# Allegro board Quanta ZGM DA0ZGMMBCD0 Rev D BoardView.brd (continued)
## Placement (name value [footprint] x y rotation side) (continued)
D73  *ESD5311Z-2/TR  [D-0_6X0_3-0_34H]  18.34 16.98 0 bottom
D74  *ESD5311Z-2/TR  [D-0_6X0_3-0_34H]  19.32 16.98 180 bottom
D75  *ESD5311Z-2/TR  [D-0_6X0_3-0_34H]  20.42 16.98 0 bottom
D76  *ESD5311Z-2/TR  [D-0_6X0_3-0_34H]  21.4 16.98 180 bottom
D77  *ESD5311Z-2/TR  [D-0_6X0_3-0_34H]  22.5 16.98 0 bottom
D78  *ESD5311Z-2/TR  [D-0_6X0_3-0_34H]  23.48 16.98 180 bottom
D79  *ESD5311Z-2/TR  [D-0_6X0_3-0_34H]  24.59 16.98 0 bottom
D80  *ESD5311Z-2/TR  [D-0_6X0_3-0_34H]  25.61 16.98 180 bottom
DG1  BAT54AW-L  [SOT23-1_7-65-3P]  245.39 113.12 0 top
DG2  RB500V-40  [D-SOD323-1_85X1_25-0_95H]  262.89 116.55 90 bottom
DG3  RB500V-40  [D-SOD323-1_85X1_25-0_95H]  248.64 116.23 270 bottom
DG4  RB500V-40  [D-SOD323-1_85X1_25-0_95H]  250.52 116.2 90 bottom
DG5  RB500V-40  [D-SOD323-1_85X1_25-0_95H]  252.37 116.2 270 bottom
DG6  RB500V-40  [D-SOD323-1_85X1_25-0_95H]  254.33 116.2 90 bottom
EC1  *10p/25V_2  [C0201]  266.37 191.91 0 bottom
ESD1  *AZ1045-04F.R7G  [ESD10-2_5X1-5-9P-AZ1143]  17.44 9.82 90 top
HOLE1  *H-C94D94N  [H-C94D94N]  155.9 219.35 0 top
HOLE2  *H-C94D94N  [H-C94D94N]  237.9 219.35 0 top
HOLE3  *H-C315D118P2  [H-C315D118P2]  155.9 214.1 0 top
HOLE4  *H-TC315IC158BC236D118P2  [H-TC315IC158BC236D118P2]  197.9 214.1 0 top
HOLE5  *H-TBC315IC158D118P2  [H-TBC315IC158D118P2]  239.9 214.1 0 top
HOLE6  *H-ZGM-3  [H-ZGM-3]  109.9 213.6 0 top
HOLE7  *H-C114D114N  [H-C114D114N]  280.4 213.6 0 top
HOLE8  *H-ZGM-2  [H-ZGM-2]  285.9 213.6 0 top
HOLE9  *H-TC315IC198BC158D158PT  [H-TC315IC198BC158D158PT]  200.54 174.56 0 top
HOLE10  *H-TC315IC198BC158D158PT  [H-TC315IC198BC158D158PT]  273.86 174.56 0 top
HOLE11  *H-TC315IC198BC158D158PT  [H-TC315IC198BC158D158PT]  123.79 167.07 0 top
HOLE12  *H-TC315IC198BC158D158PT  [H-TC315IC198BC158D158PT]  176.59 167.07 0 top
HOLE13  *H-TC315IC158BC236D118P2  [H-TC315IC158BC236D118P2]  286.1 150 0 top
HOLE15  *H-TC315IC198BC158D158PT  [H-TC315IC198BC158D158PT]  200.54 119.58 0 top
HOLE16  *H-TC315IC198BC158D158PT  [H-TC315IC198BC158D158PT]  273.86 119.58 0 top
HOLE17  *H-TC315IC198BC158D158PT  [H-TC315IC198BC158D158PT]  123.79 117.07 0 top
HOLE18  *H-TC315IC198BC158D158PT  [H-TC315IC198BC158D158PT]  176.59 117.07 0 top
HOLE19  *H-C315I158D118P2  [H-C315I158D118P2]  295.72 113.71 0 top
HOLE20  *H-TBC315IC158D118P2  [H-TBC315IC158D118P2]  99.13 109.14 0 top
HOLE21  *H-C315D276P2  [H-C315D276P2]  208.86 90.77 0 top
HOLE22  *H-C315D118P2  [H-C315D118P2]  17.4 87 0 top
HOLE24  *H-TC146IC186BC228D146P2  [H-TC146IC186BC228D146P2]  112.88 71.95 180 bottom
HOLE25  *2d-barcode-8x8-s  [2D-BARCODE-8X8-S]  85.86 69.18 180 top
HOLE26  *H-ZGM-1  [H-ZGM-1]  291.4 63.2 0 top
HOLE27  *H-C315D118P2  [H-C315D118P2]  105.32 42.5 0 top
HOLE28  *H-C315D118P2  [H-C315D118P2]  253.5 42.5 0 top
HOLE29  *H-C315D118P2  [H-C315D118P2]  29 34.5 0 top
HOLE30  *H-C315D118P2  [H-C315D118P2]  10.4 4 0 top
HOLE31  *h-tc228ic174bc134d134pt  [H-TC228IC174BC134D134PT]  25.98 84.43 180 bottom
HOLE32  *H-TC217IC174BC134D134PT  [H-TC217IC174BC134D134PT]  249.41 70.24 180 bottom
HOLE33  *h-tc228ic174bc134d134pt  [H-TC228IC174BC134D134PT]  25.98 59.43 180 bottom
HOLE34  *2d-barcode-8x8-s  [2D-BARCODE-8X8-S]  92.89 45.56 0 bottom
HOLE35  *pad-zgm-1np  [PAD-ZGM-1NP]  280.8 112.87 180 bottom
HOLE36  *pad-zgm-2np  [PAD-ZGM-2NP]  263.02 112.87 180 bottom
HOLE37  *pad-zgm-3np  [PAD-ZGM-3NP]  217.3 112.87 180 bottom
HOLE38  *pad-zgm-4np  [PAD-ZGM-4NP]  181.74 112.87 180 bottom
HOLE39  *pad-zgm-5np  [PAD-ZGM-5NP]  166.5 112.87 180 bottom
HOLE40  *pad-zgm-6np  [PAD-ZGM-6NP]  120.78 112.87 180 bottom
HOLE41  *pad-zgm-7np  [PAD-ZGM-7NP]  118.24 133.19 180 bottom
HOLE42  *pad-zgm-8np  [PAD-ZGM-8NP]  118.24 171.29 180 bottom
HOLE43  *pad-zgm-9np  [PAD-ZGM-9NP]  128.4 171.29 180 bottom
HOLE44  *pad-zgm-10np  [PAD-ZGM-10NP]  161.42 171.29 180 bottom
HOLE45  *pad-zgm-11np  [PAD-ZGM-11NP]  194.44 173.83 180 bottom
HOLE46  *pad-zgm-12np  [PAD-ZGM-12NP]  222.38 189.07 180 bottom
HOLE47  *pad-zgm-13np  [PAD-ZGM-13NP]  247.78 189.07 180 bottom
HOLE48  *pad-zgm-14np  [PAD-ZGM-14NP]  270.64 189.07 180 bottom
HOLE49  *pad-zgm-15np  [PAD-ZGM-15NP]  280.8 171.29 180 bottom
HOLE50  *pad-zgm-16np  [PAD-ZGM-16NP]  280.8 148.43 180 bottom
J1  5G@5-501709002000-6  [SIMCARD-5-501709002000-6-6P]  238.73 68 0 bottom
J2  5G_S@20449-001E-03  [ANTENNA-20449-001E-4P]  270.76 53 90 bottom
J3  5G_S@20449-001E-03  [ANTENNA-20449-001E-4P]  275.76 53 90 bottom
J4  *JUMP  [JOPEN25X30_S]  226.83 51.73 180 bottom
J5  *JUMP  [JOPEN25X30_S]  231.52 47.84 0 bottom
JDIM1  D4AS0-26001-1P80  [DDR4-D4AS0-26001-1P80-STD-260P-SMT]  154.7 100.25 0 bottom
JDIM2  D4AS0-26001-1P40  [DDR4-D4AS0-26001-1P40-STD-260P-SMT]  154.65 85.45 0 bottom
L1  BLM15PD121SN1D_1.3A  [R0402]  55.88 95.72 90 top
L2  0.68uH_2.5x2.0x1.2  [L2_5X2-1_2H]  44.83 94.45 0 top
L3  *NFP0QHB372HS2D  [FILTER-NFG0QHB372HS2D-4P-SMT]  210.52 80.89 270 top
L4  BLM15PD121SN1D_1.3A  [R0402]  48.64 77.81 90 top
L5  PBY160808T-600Y-N_3A  [R0603]  310.56 77.72 90 top
L6  0.68uH_2.5x2.0x1.2  [L2_5X2-1_2H]  40.26 77.18 0 top
L7  BLM15AG121SN1D_0.5A  [R0402]  169.04 75.53 270 top
L8  HCB2012KF-220T60_6A  [R0805]  314.31 74.62 90 top
L9  *SUB@0_5%_6  [R0603]  297.02 72.9 270 top
L10  *SUB@0_5%_6  [R0603]  298.45 74.17 270 top
L11  PBY160808T-600Y-N_3A  [R0603]  305.84 69.52 180 top
L12  HCB1608KF-301T20_2A  [R0603]  14.51 67.98 180 top
L13  BLM15AG121SN1D_0.5A  [R0402]  186.57 64.22 0 top
L14  BLM15AG121SN1D_0.5A  [R0402]  187.96 62.83 90 top
L15  RFL11T2SA0BR  [FILTER-RFL11T2SA0BR-6P]  19.08 56.96 270 top
L16  RFA11T2SA4CR  [FILTER-RFL11T2SA0BR-6P]  18.79 51.82 270 top
L17  *SUB@Short_0603  [S0603]  288.29 74.64 180 bottom
L18  *SUB@Short_0603  [S0603]  288.67 69.94 0 bottom
L19  HCB1608KF-301T20_2A  [R0603]  24.21 66.66 90 bottom
L20  PBY160808T-600Y-N_3A  [R0603]  309.75 61.42 180 bottom
L21  SUB@HCB2012KF-220T60_6A  [R0805]  299.04 60.6 0 bottom
L22  PBY160808T-600Y-N_3A  [R0603]  314.48 60.36 180 bottom
LED1  *B/R/G_LTST-G683GEBW-P2  [LEDLTST-G683GEBW-6P]  197.9 219.15 0 bottom
LED2  *B/R/G_LTST-G683GEBW-P2  [LEDLTST-G683GEBW-6P]  148.9 218.65 0 bottom
LED3  *B/R/G_LTST-G683GEBW-P2  [LEDLTST-G683GEBW-6P]  162 218.65 180 bottom
LED4  *B/R/G_LTST-G683GEBW-P2  [LEDLTST-G683GEBW-6P]  169.9 218.65 0 bottom
LED5  *B/R/G_LTST-G683GEBW-P2  [LEDLTST-G683GEBW-6P]  226.9 218.65 180 bottom
LED6  *B/R/G_LTST-G683GEBW-P2  [LEDLTST-G683GEBW-6P]  233.9 218.65 0 bottom
LED7  *B/R/G_LTST-G683GEBW-P2  [LEDLTST-G683GEBW-6P]  246 218.65 180 bottom
LG1  HCB1005KF-330T30_3A  [R0402]  266.09 136.96 180 top
LG2  HCB1005KF-330T30_3A  [R0402]  225.22 133.59 0 top
LG6  5G@HCB1005KF-330T30_3A  [R0402]  237.32 59.6 180 bottom
LG7  5G@HCB1005KF-330T30_3A  [R0402]  239.47 59.6 0 bottom
LG8  5G@HCB1005KF-330T30_3A  [R0402]  241.61 59.6 0 bottom
NOREF  -  []  115.45 -71.59 0 top
NOREF#2  -  [unnamed#2]  320.17 60.41 0 top
NOREF#3  -  [unnamed#2]  31.24 70.29 0 top
NOREF#4  -  [unnamed#2]  9.66 99.91 0 top
NOREF#5  -  []  88.4 44.31 0 top
NOREF#6  -  [unnamed#2]  285.73 207.73 0 top
NOREF#7  -  [unnamed#2]  41.3 87.34 90 top
NOREF#8  -  []  167.54 -10.4 0 top
NOREF#9  -  []  85.93 55.21 180 bottom
NOREF#10  -  [unnamed#2]  320.32 60.58 180 bottom
NOREF#11  -  [unnamed#2]  283.83 56.35 270 bottom
NOREF#12  -  [unnamed#2]  285.64 207.98 180 bottom
NOREF#13  -  [unnamed#2]  9.67 100.07 180 bottom
PC1  EV@1000p/50V_4  [C0402]  223.86 215.11 0 top
PC2  *EV@0.015u/25V_4  [C0402]  233.9 214.5 0 top
PC3  0.1u/6.3V_2  [C0201]  124.67 213.8 0 top
PC4  EV@1u/6.3V_4  [C0402]  223.05 212.52 90 top
PC5  *0.47u/10V_4  [C0402]  169.89 212.31 0 top
PC6  *EV@0.1u/25V_2  [C0201]  251.34 212.16 0 top
PC7  330p/50V_4  [C0402]  162.97 211.92 90 top
PC8  *0.1u/16V_4  [C0402]  168.06 211.51 270 top
PC9  2.2u/6.3V_4  [C0402]  165.71 210.82 270 top
PC10  330p/25V_4  [C0402]  170.44 210.15 0 top
PC11  G3@0.1u/25V_4  [C0402]  136.24 209.84 180 top
PC12  330p/25V_4  [C0402]  169.42 209.18 180 top
PC13  33p/50V_4  [C0402]  168.02 209 270 top
PC14  6800p/50V_4  [C0402]  161.53 208.09 180 top
PC15  EV@0.1u/50V_4  [C0402]  228.94 208.07 0 top
PC16  EV@680p/50V_4  [C0402]  226.57 207.71 270 top
PC17  EV@0.1u/50V_4  [C0402]  256.72 206.23 90 top
PC18  EV@2200p/50V_4  [C0402]  255.63 206.23 90 top
PC19  EV@0.1u/50V_4  [C0402]  254.53 206.23 90 top
PC20  0.1u/25V_4  [C0402]  167.95 206.13 270 top
PC21  EV@2200p/50V_4  [C0402]  238.98 206.09 90 top
PC22  EV@0.1u/50V_4  [C0402]  241 206.07 90 top
PC23  EV@0.1u/50V_4  [C0402]  239.98 206.07 90 top
PC24  *EV@0.015u/25V_4  [C0402]  225.89 205.98 270 top
PC25  0.1u/50V_4  [C0402]  172.42 205.09 180 top
PC26  2.2u/6.3V_4  [C0402]  162.31 204.69 0 top
PC27  EV@10u/25V_8  [C0805]  248.29 204.64 90 top
PC28  EV@10u/25V_8  [C0805]  252.62 204.64 90 top
PC29  0.22u/25V_4  [C0402]  163.83 203.32 90 top
PC30  *EV@2200p/50V_4  [C0402]  233.43 200.43 0 top
PC31  *EV@47u/6.3V_6  [C0603]  243.63 196.57 270 top
PC32  10u/25V_8  [C0805]  173.99 196.57 90 top
PC33  *EV@47u/6.3V_6  [C0603]  242.17 196.56 270 top
PC34  EV@47u/6.3V_6  [C0603]  245.08 196.55 270 top
PC35  2200p/50V_4  [C0402]  175.52 196.3 90 top
PC36  EV@330u/2V_7343H1.9  [CC7343]  253.02 195.17 90 top
PC37  EV@330u/2V_7343H1.9  [CC7343]  248.24 195.17 90 top
PC38  EV@330u/2V_7343H1.9  [CC7343]  234.17 195.14 90 top
PC39  EV@330u/2V_7343H1.9  [CC7343]  238.92 195.14 90 top
PC40  10u/25V_8  [C0805]  118.11 194.65 90 top
PC41  10u/25V_8  [C0805]  127.77 194.65 90 top
PC42  10u/25V_8  [C0805]  137.42 194.65 90 top
PC43  10u/25V_8  [C0805]  147.07 194.65 90 top
PC44  10u/25V_8  [C0805]  156.72 194.65 90 top
PC45  10u/25V_8  [C0805]  166.37 194.65 90 top
PC46  *2200p/50V_4  [C0402]  175.36 193.03 270 top
PC47  G3@0.1u/25V_2  [C0201]  227.72 191.71 90 top
PC48  G3@0.1u/25V_2  [C0201]  229.01 191.03 90 top
PC49  G3@0.1u/25V_2  [C0201]  227.72 190.71 90 top
PC50  *EV@47u/6.3V_6  [C0603]  243.69 190.67 90 top
PC51  *EV@47u/6.3V_6  [C0603]  242.24 190.67 90 top
PC52  EV@47u/6.3V_6  [C0603]  245.13 190.67 90 top
PC53  G3@0.1u/25V_4  [C0402]  223.19 189.07 270 top
PC54  G3@0.1u/25V_4  [C0402]  227.65 188.44 270 top
PC55  1000p/50V_4  [C0402]  116.97 188.3 0 top
PC56  1000p/50V_4  [C0402]  126.62 188.3 0 top
PC57  1000p/50V_4  [C0402]  136.4 188.3 0 top
PC58  1000p/50V_4  [C0402]  155.71 188.3 0 top
PC59  1000p/50V_4  [C0402]  165.23 188.3 0 top
PC60  1000p/50V_4  [C0402]  145.93 188.18 0 top
PC61  330u/2.5V_7343H1.9  [CC7343]  168.94 185.85 90 top
PC62  *330u/2.5V_7343H1.9  [CC7343]  173.88 185.75 90 top
PC63  330u/2V_7343H1.9  [CC7343]  123.7 182.84 90 top
PC64  *330u/2V_7343H1.9  [CC7343]  133.35 182.84 90 top
PC65  330u/2V_7343H1.9  [CC7343]  143.01 182.84 90 top
PC66  330u/2V_7343H1.9  [CC7343]  152.66 182.84 90 top
PC67  220u/2V_7343H1.0  [CC7343]  143.07 140.99 0 top
PC68  220u/2V_7343H1.0  [CC7343]  143.07 145.75 0 top
PC69  22u/6.3V_6  [C0603]  174.7 179.76 180 top
PC70  22u/6.3V_6  [C0603]  168.97 179.72 0 top
PC71  22u/6.3V_8  [C0805]  111.67 179.04 270 top
PC72  22u/6.3V_8  [C0805]  165.8 179.03 270 top
PC73  22u/6.3V_8  [C0805]  118.38 178.92 270 top
PC74  22u/6.3V_8  [C0805]  120.36 178.92 270 top
PC75  22u/6.3V_8  [C0805]  146.82 178.91 270 top
PC76  22u/6.3V_8  [C0805]  149.23 178.91 270 top
PC77  22u/6.3V_8  [C0805]  156.47 178.91 270 top
PC78  22u/6.3V_8  [C0805]  158.88 178.91 270 top
PC79  22u/6.3V_8  [C0805]  127.38 178.78 270 top
PC80  22u/6.3V_8  [C0805]  129.8 178.78 270 top
PC81  22u/6.3V_8  [C0805]  137.16 178.78 270 top
PC82  22u/6.3V_8  [C0805]  139.58 178.78 270 top
PC83  22u/6.3V_6  [C0603]  168.92 177.89 0 top
PC84  22u/6.3V_6  [C0603]  174.82 177.81 180 top
PC85  22u/6.3V_6  [C0603]  168.89 176.08 0 top
PC86  0.1u/50V_4  [C0402]  158.32 175.21 90 top
PC87  0.1u/50V_4  [C0402]  111.33 175.2 90 top
PC88  0.1u/50V_4  [C0402]  130.17 175.2 90 top
PC89  0.1u/50V_4  [C0402]  139.31 175.2 90 top
PC90  0.1u/50V_4  [C0402]  120.25 175.2 90 top
PC91  0.1u/50V_4  [C0402]  149.21 175.2 90 top
PC92  EV@0.1u/16V_4  [C0402]  283.34 130.21 90 top
PC93  *EV@22u/6.3V_6  [C0603]  286.13 130.13 90 top
PC94  EV@22u/6.3V_6  [C0603]  284.67 130.13 90 top
PC95  EV@22u/6.3V_6  [C0603]  287.59 130.12 90 top
PC96  EV@2.2u/10V_4  [C0402]  290.38 124.97 180 top
PC97  EV@0.1u/25V_4  [C0402]  286.04 123.9 180 top
PC98  EV@1u/6.3V_4  [C0402]  291.92 122.78 180 top
PC99  EV@330p/25V_2  [C0201]  291.61 121.85 180 top
PC100  EV@22u/6.3V_6  [C0603]  284.12 121.15 0 top
PC101  EV@0.1u/16V_4  [C0402]  290.43 119.26 270 top
PC102  *EV@2200p/50V_4  [C0402]  289.96 116.93 90 top
PC103  EV@330u/2V_7343H1.9  [CC7343]  232.29 103.98 270 top
PC104  EV@330u/2V_7343H1.9  [CC7343]  238 103.98 270 top
PC105  EV@330u/2V_7343H1.9  [CC7343]  242.83 103.98 270 top
PC106  EV@330u/2V_7343H1.9  [CC7343]  247.78 103.98 270 top
PC107  EV@330u/2V_7343H1.9  [CC7343]  252.61 103.98 270 top
PC108  EV@330u/2V_7343H1.9  [CC7343]  257.56 103.98 270 top
PC109  EV@330u/2V_7343H1.9  [CC7343]  262.39 103.98 270 top
PC110  EV@330u/2V_7343H1.9  [CC7343]  267.34 103.98 270 top
PC111  EV@330u/2V_7343H1.9  [CC7343]  272.16 103.98 270 top
PC112  EV@330u/2V_7343H1.9  [CC7343]  276.99 103.98 270 top
PC113  EV@330u/2V_7343H1.9  [CC7343]  281.82 103.98 270 top
PC114  G3@330u/2V_7343H1.9  [CC7343]  286.9 103.98 270 top
PC115  G3@330u/2V_7343H1.9  [CC7343]  291.72 103.98 270 top
PC116  5G@0.1u/16V_4  [C0402]  301.26 103.97 180 top
PC117  EV@330u/2V_7343H1.9  [CC7343]  227.41 103.93 270 top
PC118  EV@330u/2V_7343H1.9  [CC7343]  215.12 103.9 270 top
PC119  EV@330u/2V_7343H1.9  [CC7343]  219.99 103.87 270 top
PC120  EV@0.1u/50V_4  [C0402]  198.36 103.37 270 top
PC121  5G@330p/25V_2  [C0201]  295.81 102.1 0 top
PC122  5G@22u/6.3V_6  [C0603]  301.72 102.7 180 top
PC123  10u/25V_6  [C0603]  97.48 94.99 180 top
PC124  10u/25V_6  [C0603]  85.98 93.31 270 top
PC125  10u/25V_6  [C0603]  87.51 93.31 270 top
PC126  EV@10u/25V_8  [C0805]  224.79 93.31 270 top
PC127  EV@10u/25V_8  [C0805]  234.57 93.31 270 top
PC128  EV@10u/25V_8  [C0805]  244.35 93.31 270 top
PC129  EV@10u/25V_8  [C0805]  254.13 93.31 270 top
PC130  EV@10u/25V_8  [C0805]  263.91 93.31 270 top
PC131  EV@10u/25V_8  [C0805]  273.69 93.31 270 top
PC132  G3@10u/25V_8  [C0805]  292.75 93.29 270 top
PC133  EV@10u/25V_8  [C0805]  283.72 93.18 270 top
PC134  10u/25V_6  [C0603]  97.48 93.56 180 top
PC135  0.1u/25V_4  [C0402]  89.49 93.05 270 top
PC136  10u/25V_6  [C0603]  96.67 90.96 180 top
PC137  G3@10u/25V_8  [C0805]  292.74 90.03 90 top
PC138  EV@10u/25V_8  [C0805]  224.79 90.01 90 top
PC139  EV@10u/25V_8  [C0805]  234.57 90.01 90 top
PC140  EV@10u/25V_8  [C0805]  244.35 90.01 90 top
PC141  EV@10u/25V_8  [C0805]  254.13 90.01 90 top
PC142  EV@10u/25V_8  [C0805]  263.91 90.01 90 top
PC143  EV@10u/25V_8  [C0805]  273.69 90.01 90 top
PC144  EV@10u/25V_8  [C0805]  283.72 89.88 90 top
PC145  10u/25V_6  [C0603]  96.67 89.53 180 top
PC146  0.1u/25V_4  [C0402]  88.56 89.26 180 top
PC147  G3@0.1u/50V_4  [C0402]  291.24 88.91 90 top
PC148  EV@0.1u/50V_4  [C0402]  282.07 89.12 90 top
PC149  0.1u/25V_4  [C0402]  97.14 86.96 270 top
PC150  4.7u/6.3V_4  [C0402_2]  89.39 85.19 90 top
PC151  10p/50V_4  [C0402]  92.08 85.18 90 top
PC152  2200p/25V_2  [C0201]  93.48 84.14 270 top
PC153  EV@1u/10V_2  [C0201]  262.51 83.91 270 top
PC154  *EV@1500p/50V_4  [C0402]  264.67 83.53 90 top
PC155  *EV@0.047u/25V_4  [C0402]  277.7 83.4 90 top
PC156  EV@33u/25V_7343H1.9  [CC7343]  241.47 83.02 180 top
PC157  EV@4700p/50V_4  [C0402]  267.97 81.88 0 top
PC158  EV@4.7u/6.3V_2  [C0201]  256.59 80.51 90 top
PC159  EV_SP@220p/50V_2  [C0201]  251.72 79.85 0 top
PC160  EV@220p/50V_2  [C0201]  251.73 79.04 0 top
PC161  EV@220p/50V_2  [C0201]  251.74 77.95 0 top
PC162  EV@220p/50V_2  [C0201]  251.72 77.19 180 top
PC163  EV@0.1u/25V_4  [C0402]  266.07 76.29 180 top
PC164  EV@220p/50V_2  [C0201]  251.73 76.1 0 top
PC165  *EV@0.015u/25V_4  [C0402]  267.47 75.65 270 top
PC166  1000p/50V_2  [C0201]  130.43 75.48 90 top
PC167  1000p/50V_2  [C0201]  131.19 75.48 90 top
PC168  EV@220p/50V_2  [C0201]  251.72 75.34 180 top
PC169  *EV@0.015u/25V_4  [C0402]  266.07 75.32 0 top
PC170  1000p/50V_2  [C0201]  144.15 74.61 90 top
PC171  1000p/50V_2  [C0201]  144.91 74.61 90 top
PC172  1000p/50V_2  [C0201]  55.63 74.26 90 top
PC173  1000p/50V_2  [C0201]  56.39 74.26 90 top
PC174  EV@220p/50V_2  [C0201]  251.72 74.26 0 top
PC175  10u/6.3V_4  [C0402_2]  127.64 74.13 90 top
PC176  0.1u/50V_4  [C0402]  128.78 74.13 90 top
PC177  10u/6.3V_4  [C0402_2]  133.53 74.13 90 top
PC178  0.1u/50V_4  [C0402]  134.62 74.13 90 top
PC179  *EV@0.1u/25V_2  [C0201]  265.81 74.05 0 top
PC180  *EV@0.1u/25V_2  [C0201]  266.96 74.03 180 top
PC181  EV@220p/50V_2  [C0201]  251.72 73.44 180 top
PC182  10u/6.3V_4  [C0402_2]  141.35 73.24 90 top
PC183  0.1u/50V_4  [C0402]  142.5 73.24 90 top
PC184  10u/6.3V_4  [C0402_2]  147.25 73.24 90 top
PC185  0.1u/50V_4  [C0402]  148.34 73.24 90 top
PC186  10u/6.3V_4  [C0402_2]  52.33 72.66 90 top
PC187  0.1u/50V_4  [C0402]  53.47 72.66 90 top
PC188  *EV@1000p/50V_2  [C0201]  263.91 72.48 270 top
PC189  1u/25V_4  [C0402]  128.53 72.38 270 top
PC190  1u/25V_4  [C0402]  133.61 72.35 270 top
PC191  EV@1u/6.3V_2  [C0201]  257.18 72.35 270 top
PC192  EV@0.015u/25V_4  [C0402]  264.8 72.1 270 top
PC193  *EV@1000p/50V_2  [C0201]  259.72 71.97 270 top
PC194  *EV@1000p/50V_2  [C0201]  265.69 71.97 90 top
PC195  EV@0.1u/50V_4  [C0402]  262.39 71.59 180 top
PC196  1u/25V_4  [C0402]  142.5 71.46 270 top
PC197  1u/25V_4  [C0402]  147.25 71.39 270 top
PC198  1u/25V_4  [C0402]  58.17 71.06 270 top
PC199  1u/25V_4  [C0402]  53.47 70.93 270 top
PC200  *0.1u/50V_4  [C0402]  129.82 70.6 90 top
PC201  0.1u/50V_4  [C0402]  130.8 70.59 90 top
PC202  *0.1u/50V_4  [C0402]  132.6 70.52 90 top
PC203  0.1u/50V_4  [C0402]  144.58 69.59 90 top
PC204  *0.1u/50V_4  [C0402]  143.61 69.58 90 top
PC205  *0.1u/50V_4  [C0402]  147.05 69.57 90 top
PC206  *0.1u/50V_4  [C0402]  54.54 68.89 90 top
PC207  *2200p/50V_4  [C0402]  263.44 67.49 90 top
PC208  10u/6.3V_4  [C0402_2]  267.22 64.99 180 top
PC209  0.01u/50V_4  [C0402]  267.22 63.83 180 top
PC210  4.7u/6.3V_2  [C0201]  154.05 61.99 90 top
PC211  *22p/50V_4  [C0402]  265.05 61.31 270 top
PC212  0.1u/50V_4  [C0402]  157.18 59.53 180 top
PC213  0.1u/50V_4  [C0402]  149.99 59.4 0 top
PC214  2200p/50V_4  [C0402]  250.96 58.66 0 top
PC215  10u/6.3V_6  [C0603]  66.27 56.85 270 top
PC216  0.1u/50V_4  [C0402]  67.47 56.46 270 top
PC217  1000p/50V_4  [C0402]  68.49 56.46 270 top
PC218  1000p/50V_4  [C0402]  69.51 56.46 270 top
PC219  0.1u/50V_4  [C0402]  152.76 55.18 180 top
PC220  10u/6.3V_4  [C0402_2]  155.12 55.03 180 top
PC221  *2200p/50V_4  [C0402]  53.63 54.67 270 top
PC222  *680p/50V_6  [C0603]  152.58 51.73 180 top
PC223  0.1u/50V_4  [C0402]  172.01 51.69 180 top
PC224  *680p/50V_6  [C0603]  160.89 51.63 0 top
PC225  0.1u/50V_4  [C0402]  69.65 51.19 270 top
PC226  0.1u/50V_4  [C0402]  71.68 51.19 90 top
PC227  0.1u/50V_4  [C0402]  67.9 50.89 90 top
PC228  1u/25V_4  [C0402]  66.61 50.68 90 top
PC229  0.1u/50V_4  [C0402]  48.28 50.5 270 top
PC230  2200p/50V_4  [C0402]  49.25 50.5 270 top
PC231  680p/50V_4  [C0402]  50.22 50.5 90 top
PC232  1000p/50V_4  [C0402]  51.2 50.5 270 top
PC233  22u/6.3V_8  [C0805]  127.1 48.5 90 top
PC234  22u/6.3V_8  [C0805]  129.11 48.5 90 top
PC235  0.1u/50V_4  [C0402]  39.5 47.46 90 top
PC236  0.1u/50V_4  [C0402]  40.9 47.46 270 top
PC237  0.1u/50V_4  [C0402]  57.78 47.36 270 top
PC238  0.01u/50V_4  [C0402]  36.5 46.45 270 top
PC239  0.1u/50V_4  [C0402]  39.88 46.06 180 top
PC240  330u/2V_7343H1.9  [CC7343]  132.49 45.38 270 top
PC241  *0.01u/50V_4  [C0402]  59.21 45.32 90 top
PC242  100p/50V_2  [C0201]  33.91 45.17 0 top
PC243  0.47u/25V_4  [C0402]  42.55 44.81 180 top
PC244  100p/50V_2  [C0201]  33.79 44.03 0 top
PC245  0.1u/25V_4  [C0402]  238.38 43.52 180 top
PC246  10u/25V_6  [C0603]  245.41 42.96 270 top
PC247  22u/25V_8  [C0805]  62.23 42.63 90 top
PC248  22u/25V_8  [C0805]  64.27 42.63 90 top
PC249  *22u/25V_8  [C0805]  66.3 42.63 90 top
PC250  *22u/25V_8  [C0805]  68.33 42.63 90 top
PC251  0.1u/50V_6  [C0603]  70.06 42.63 90 top
PC252  *100p/50V_4  [C0402]  59.67 42.51 90 top
PC253  2200p/50V_4  [C0402]  60.71 42.51 90 top
PC254  2200p/25V_2  [C0201]  246.59 42.33 90 top
PC255  220u/2.5V_7343H1.0  [CC7343]  232.46 42.3 0 top
PC256  *47p/50V_4  [C0402]  73.66 42 90 top
PC257  *47p/50V_4  [C0402]  76.97 42 90 top
PC258  0.1u/50V_4  [C0402]  125.94 41.6 180 top
PC259  0.047u/50V_4  [C0402]  42.85 41.19 0 top
PC260  *100p/50V_2  [C0201]  33.23 41.03 90 top
PC261  10u/25V_6  [C0603]  245.51 40.28 90 top
PC262  10u/25V_8  [C0805]  126.68 40.1 180 top
PC263  0.01u/50V_4  [C0402]  41.14 39.84 270 top
PC264  2.2u/10V_4  [C0402]  42.16 39.84 90 top
PC265  0.1u/25V_4  [C0402]  246.7 39.38 90 top
PC266  0.1u/25V_2  [C0201]  39.43 39.37 180 top
PC267  0.1u/25V_2  [C0201]  38.45 39.37 0 top
PC268  *680p/50V_6  [C0603]  132.93 39.25 180 top
PC269  *22u/6.3V_6  [C0603]  233.94 39.21 180 top
PC270  *680p/50V_6  [C0603]  53.22 38.82 180 top
PC271  0.1u/25V_4  [C0402]  238.13 38.7 0 top
PC272  0.1u/25V_2  [C0201]  38.97 38.66 180 top
PC273  *22u/6.3V_6  [C0603]  226.75 38.19 90 top
PC274  *22u/6.3V_6  [C0603]  228.22 38.19 90 top
PC275  *22u/6.3V_6  [C0603]  229.67 38.19 90 top
PC276  22u/6.3V_6  [C0603]  233.94 37.78 180 top
PC277  *2200p/25V_2  [C0201]  234.95 36.64 0 top
PC278  0.1u/16V_4  [C0402]  117.22 216.75 180 bottom
PC279  EV@1u/25V_4  [C0402]  252.62 216.35 90 bottom
PC280  *100p/50V_4  [C0402]  124.47 215.94 270 bottom
PC281  *EV@0.1u/25V_2  [C0201]  251.62 215.39 0 bottom
PC282  EV@0.1u/25V_4  [C0402]  250.65 215.26 270 bottom
PC283  EV@1000p/50V_4  [C0402]  223.18 215.02 0 bottom
PC284  2.2u/10V_4  [C0402]  116.93 214.78 270 bottom
PC285  *EV@56p/25V_2  [C0201]  253.72 214.68 90 bottom
PC286  EV@1000p/50V_4  [C0402]  246.78 214.63 0 bottom
PC287  1000p/50V_4  [C0402]  124.84 214.59 180 bottom
PC288  *100p/50V_4  [C0402]  126.62 214.59 180 bottom
PC289  *EV@56p/25V_2  [C0201]  252.22 214.53 90 bottom
PC290  *0.1u/6.3V_2  [C0201]  122.38 214.39 270 bottom
PC291  *0.1u/6.3V_2  [C0201]  123.1 214.39 270 bottom
PC292  *EV@1000p/50V_4  [C0402]  228.04 214.07 90 bottom
PC293  G3@680p/50V_4  [C0402]  223.18 214.05 0 bottom
PC294  *EV@56p/25V_2  [C0201]  252.12 213.67 180 bottom
PC295  2200p/50V_4  [C0402]  124.84 213.58 0 bottom
PC296  G3@1000p/50V_4  [C0402]  223.18 213.08 180 bottom
PC297  0.01u/50V_4  [C0402]  115.31 212.99 180 bottom
PC298  *EV@1000p/16V_2  [C0201]  252.74 212.92 0 bottom
PC299  470p/25V_2  [C0201]  124.46 212.69 180 bottom
PC300  G3@0.1u/50V_4  [C0402]  223.18 212.12 180 bottom
PC301  470p/50V_4  [C0402]  124.83 211.65 180 bottom
PC302  *EV@820p/50V_4  [C0402]  245.89 211.49 0 bottom
PC303  *EV@0.015u/25V_4  [C0402]  231.42 211.37 180 bottom
PC304  G3@2200p/50V_4  [C0402]  223.18 211.15 180 bottom
PC305  *1000p/25V_2  [C0201]  115.58 210.19 0 bottom
PC306  G3@0.1u/50V_4  [C0402]  223.18 210.19 180 bottom
PC307  *EV@1000p/50V_4  [C0402]  229.58 210 270 bottom
PC308  *EV@1000p/50V_4  [C0402]  228.35 209.98 270 bottom
PC309  *EV@0.015u/25V_4  [C0402]  230.57 210.02 90 bottom
PC310  EV@0.22u/25V_4  [C0402]  252.72 209.79 180 bottom
PC311  2200p/50V_4  [C0402]  126.88 209.77 0 bottom
PC312  0.1u/50V_4  [C0402]  172.85 209.69 180 bottom
PC313  47p/50V_4  [C0402]  124.83 209.62 0 bottom
PC314  EV@0.22u/25V_4  [C0402]  247.14 209.46 0 bottom
PC315  1000p/50V_4  [C0402]  172.84 208.71 180 bottom
PC316  220p/50V_4  [C0402]  125.18 208.25 90 bottom
PC317  2200p/50V_4  [C0402]  126.14 208.25 90 bottom
PC318  0.1u/50V_4  [C0402]  172.83 207.74 180 bottom
PC319  33u/25V_7343H1.9  [CC7343]  132.08 207.73 90 bottom
PC320  0.1u/25V_4  [C0402]  115.21 207.43 180 bottom
PC321  EV@2.2u/10V_4  [C0402]  249.95 207.35 180 bottom
PC322  2200p/50V_4  [C0402]  172.82 206.77 180 bottom
PC323  0.1u/25V_4  [C0402]  121.24 205.96 90 bottom
PC324  0.01u/50V_4  [C0402]  122.22 205.96 90 bottom
PC325  0.1u/25V_4  [C0402]  120.04 205.95 90 bottom
PC326  0.1u/25V_4  [C0402]  117.65 205.94 90 bottom
PC327  0.1u/25V_4  [C0402]  118.81 205.94 90 bottom
PC328  0.1u/25V_4  [C0402]  116.44 205.93 90 bottom
PC329  0.1u/25V_4  [C0402]  115.29 205.92 90 bottom
PC330  680p/50V_4  [C0402]  172.84 205.8 0 bottom
PC331  *EV@2200p/50V_4  [C0402]  266.18 204.64 0 bottom
PC332  EV@10u/25V_6  [C0603]  248.3 204.59 90 bottom
PC333  EV@10u/25V_6  [C0603]  252.68 204.59 90 bottom
PC334  G3@1u/25V_4  [C0402]  225.68 203.72 270 bottom
PC335  0.22u/25V_6  [C0603]  116.18 199.56 90 bottom
PC336  0.22u/25V_6  [C0603]  125.71 199.84 90 bottom
PC337  0.22u/25V_6  [C0603]  164.32 199.58 90 bottom
PC338  0.22u/25V_6  [C0603]  135.33 199.66 90 bottom
PC339  0.22u/25V_6  [C0603]  145.21 199.66 90 bottom
PC340  0.22u/25V_6  [C0603]  154.66 199.48 90 bottom
PC341  2.2u/10V_4  [C0402]  113.29 198.97 270 bottom
PC342  2.2u/10V_4  [C0402]  122.94 198.97 90 bottom
PC343  2.2u/10V_4  [C0402]  132.59 198.97 90 bottom
PC344  2.2u/10V_4  [C0402]  142.24 198.97 90 bottom
PC345  2.2u/10V_4  [C0402]  151.9 198.97 90 bottom
PC346  2.2u/10V_4  [C0402]  161.55 198.97 90 bottom
PC347  0.1u/50V_4  [C0402]  118.11 198.34 180 bottom
PC348  0.1u/50V_4  [C0402]  127.77 198.34 180 bottom
PC349  0.1u/50V_4  [C0402]  137.42 198.34 180 bottom
PC350  0.1u/50V_4  [C0402]  147.07 198.34 180 bottom
PC351  0.1u/50V_4  [C0402]  156.72 198.34 180 bottom
PC352  0.1u/50V_4  [C0402]  166.37 198.34 180 bottom
PC353  *G3@0.1u/50V_6  [C0603]  218.04 198.02 90 bottom
PC354  2200p/50V_4  [C0402]  118.11 197.19 180 bottom
PC355  2200p/50V_4  [C0402]  127.77 197.19 180 bottom
PC356  2200p/50V_4  [C0402]  137.42 197.19 180 bottom
PC357  2200p/50V_4  [C0402]  147.07 197.19 180 bottom
PC358  2200p/50V_4  [C0402]  156.72 197.19 180 bottom
PC359  2200p/50V_4  [C0402]  166.37 197.19 180 bottom
PC360  *G3@0.1u/50V_6  [C0603]  201.73 197 90 bottom
PC361  10u/25V_8  [C0805]  174.03 196.58 90 bottom
PC362  0.1u/50V_4  [C0402]  175.52 196.3 90 bottom
PC363  *0.1u/25V_4  [C0402]  176.96 195.67 90 bottom
PC364  *0.1u/50V_6  [C0603]  187.01 195.62 0 bottom
PC365  2.2u/10V_4  [C0402]  110.11 195.42 90 bottom
PC366  2.2u/10V_4  [C0402]  119.76 195.42 90 bottom
PC367  2.2u/10V_4  [C0402]  129.42 195.42 90 bottom
PC368  2.2u/10V_4  [C0402]  139.07 195.42 90 bottom
PC369  2.2u/10V_4  [C0402]  148.72 195.42 90 bottom
PC370  2.2u/10V_4  [C0402]  158.37 195.42 90 bottom
PC371  10u/25V_6  [C0603]  118.11 194.65 90 bottom
PC372  10u/25V_6  [C0603]  127.77 194.65 90 bottom
PC373  10u/25V_6  [C0603]  137.42 194.65 90 bottom
PC374  10u/25V_6  [C0603]  147.07 194.65 90 bottom
PC375  10u/25V_6  [C0603]  156.72 194.65 90 bottom
PC376  10u/25V_6  [C0603]  166.37 194.65 90 bottom
PC377  0.047u/50V_6  [C0603]  184.15 194.61 180 bottom
PC378  *G3@0.1u/25V_4  [C0402]  219.65 193.43 270 bottom
PC379  *G3@0.1u/25V_4  [C0402]  200.65 192.96 90 bottom
PC380  *G3@0.1u/25V_4  [C0402]  214.99 192.94 270 bottom
PC381  *G3@0.1u/25V_4  [C0402]  198.64 192.47 180 bottom
PC382  G3@1u/25V_4  [C0402]  192.91 191.59 180 bottom
PC383  1000p/50V_4  [C0402]  186.29 187.82 0 bottom
PC384  1u/25V_4  [C0402]  188.17 187.82 180 bottom
PC385  22u/6.3V_6  [C0603]  174.73 179.75 180 bottom
PC386  22u/6.3V_6  [C0603]  168.95 179.73 0 bottom
PC387  *G3@0.1u/25V_4  [C0402]  178.67 179.41 0 bottom
PC388  *G3@0.1u/25V_4  [C0402]  177.11 177.95 270 bottom
PC389  22u/6.3V_6  [C0603]  168.95 177.89 0 bottom
PC390  22u/6.3V_6  [C0603]  174.77 177.81 180 bottom
PC391  22u/6.3V_6  [C0603]  168.89 176.09 0 bottom
PC392  *G3@0.1u/50V_4  [C0402]  184.25 175.38 90 bottom
PC393  0.1u/50V_4  [C0402]  108.59 129.63 180 bottom
PC394  EV@22u/6.3V_6  [C0603]  284 121.3 0 bottom
PC395  EV@0.1u/16V_4  [C0402]  284.58 119.45 0 bottom
PC396  *5G@2200p/50V_4  [C0402]  298.05 104.56 90 bottom
PC397  5G@0.1u/16V_4  [C0402]  297.09 104.42 270 bottom
PC398  EV@0.01u/50V_4  [C0402]  198.94 105.71 0 bottom
PC399  5G@1u/6.3V_4  [C0402]  295.25 103.75 0 bottom
PC400  EV@0.1u/50V_4  [C0402]  203.66 103.67 90 bottom
PC401  5G@22u/6.3V_6  [C0603]  301.73 102.71 180 bottom
PC402  5G@2.2u/10V_4  [C0402]  297.68 102.66 270 bottom
PC403  EV@0.1u/50V_4  [C0402]  207.91 101.78 90 bottom
PC404  EV@10u/6.3V_4  [C0402_2]  206.82 101.78 90 bottom
PC405  EV@10u/6.3V_4  [C0402_2]  205.61 101.77 90 bottom
PC406  5G@0.1u/16V_4  [C0402]  295.19 102.41 270 bottom
PC407  5G@22u/6.3V_6  [C0603]  296.66 100.79 180 bottom
PC408  EV@10u/6.3V_4  [C0402_2]  202.02 100.39 180 bottom
PC409  5G@0.1u/25V_4  [C0402]  299.08 100.17 270 bottom
PC410  EV@0.1u/50V_4  [C0402]  202.02 99.3 180 bottom
PC411  5G@22u/6.3V_6  [C0603]  296.63 99.36 180 bottom
PC412  *5G@22u/6.3V_6  [C0603]  296.61 97.93 180 bottom
PC413  EV@2200p/50V_4  [C0402]  282.55 97.63 90 bottom
PC414  G3@2200p/50V_4  [C0402]  294.14 97.63 90 bottom
PC415  EV@2200p/50V_4  [C0402]  234.93 97.5 90 bottom
PC416  EV@2200p/50V_4  [C0402]  244.45 97.5 90 bottom
PC417  EV@2200p/50V_4  [C0402]  253.98 97.5 90 bottom
PC418  EV@2200p/50V_4  [C0402]  263.5 97.5 90 bottom
PC419  EV@2200p/50V_4  [C0402]  273.03 97.5 90 bottom
PC420  EV@2200p/50V_4  [C0402]  225.34 97.4 90 bottom
PC421  0.1u/50V_4  [C0402]  199.72 96.43 0 bottom
PC422  *10u/6.3V_6  [C0603]  199.74 95.24 0 bottom
PC423  10u/6.3V_6  [C0603]  199.74 93.79 0 bottom
PC424  *0.47u/6.3V_4  [C0402]  197.41 93.69 0 bottom
PC425  G3@10u/25V_6  [C0603]  293.41 93.61 270 bottom
PC426  EV@10u/25V_6  [C0603]  224.46 93.43 270 bottom
PC427  EV@10u/25V_6  [C0603]  244.02 93.43 270 bottom
PC428  EV@2200p/50V_4  [C0402]  264.85 93.43 90 bottom
PC429  EV@2.2u/10V_4  [C0402]  275.73 93.42 270 bottom
PC430  G3@2.2u/10V_4  [C0402]  285.64 93.4 270 bottom
PC431  EV@2200p/50V_4  [C0402]  245.29 93.31 90 bottom
PC432  EV@10u/25V_6  [C0603]  263.58 93.31 270 bottom
PC433  EV@2200p/50V_4  [C0402]  225.73 93.18 90 bottom
PC434  EV@10u/25V_6  [C0603]  234.24 93.18 270 bottom
PC435  EV@2200p/50V_4  [C0402]  235.51 93.18 90 bottom
PC436  EV@10u/25V_6  [C0603]  253.8 93.18 270 bottom
PC437  EV@2200p/50V_4  [C0402]  255.07 93.18 90 bottom
PC438  EV@10u/25V_6  [C0603]  273.36 93.18 270 bottom
PC439  EV@2200p/50V_4  [C0402]  274.63 93.05 90 bottom
PC440  EV@10u/25V_6  [C0603]  283.39 93.05 270 bottom
PC441  EV@0.1u/50V_4  [C0402]  284.66 93.05 270 bottom
PC442  G3@0.1u/50V_4  [C0402]  294.64 93.05 270 bottom
PC443  EV@2.2u/10V_4  [C0402]  216.92 92.42 270 bottom
PC444  EV@2.2u/10V_4  [C0402]  246.26 92.37 270 bottom
PC445  EV@2.2u/10V_4  [C0402]  256.04 92.37 270 bottom
PC446  EV@2.2u/10V_4  [C0402]  226.7 92.34 270 bottom
PC447  EV@2.2u/10V_4  [C0402]  265.81 92.32 270 bottom
PC448  EV@2.2u/10V_4  [C0402]  236.48 92.29 270 bottom
PC449  G3@10u/25V_6  [C0603]  293.42 90.64 90 bottom
PC450  EV@10u/25V_6  [C0603]  283.47 90.13 90 bottom
PC451  EV@0.1u/50V_4  [C0402]  225.73 90.01 90 bottom
PC452  EV@0.1u/50V_4  [C0402]  235.51 90.01 90 bottom
PC453  EV@10u/25V_6  [C0603]  244.02 90.01 90 bottom
PC454  EV@0.1u/50V_4  [C0402]  245.29 90.01 90 bottom
PC455  EV@10u/25V_6  [C0603]  253.8 90.01 90 bottom
PC456  EV@0.1u/50V_4  [C0402]  255.07 90.01 90 bottom
PC457  EV@0.1u/50V_4  [C0402]  264.85 90.01 90 bottom
PC458  EV@10u/25V_6  [C0603]  273.36 90.01 90 bottom
PC459  EV@0.1u/50V_4  [C0402]  274.63 90.01 90 bottom
PC460  EV@10u/25V_6  [C0603]  224.46 89.88 90 bottom
PC461  EV@10u/25V_6  [C0603]  234.24 89.88 90 bottom
PC462  EV@10u/25V_6  [C0603]  263.58 89.88 90 bottom
PC463  EV@2200p/50V_4  [C0402]  284.66 89.88 270 bottom
PC464  G3@2200p/50V_4  [C0402]  294.64 90.39 270 bottom
PC465  EV@2.2u/10V_4  [C0402]  275.72 89.62 90 bottom
PC466  G3@2.2u/10V_4  [C0402]  285.63 89.62 90 bottom
PC467  4.7u/6.3V_6  [C0603]  201.55 89.14 180 bottom
PC468  EV@2.2u/10V_4  [C0402]  216.92 88.48 90 bottom
PC469  EV@2.2u/10V_4  [C0402]  226.7 88.48 90 bottom
PC470  EV@2.2u/10V_4  [C0402]  236.48 88.48 90 bottom
PC471  EV@2.2u/10V_4  [C0402]  246.26 88.48 90 bottom
PC472  EV@2.2u/10V_4  [C0402]  256.04 88.48 90 bottom
PC473  EV@2.2u/10V_4  [C0402]  265.81 88.48 90 bottom
PC474  G3@0.1u/25V_4  [C0402]  293.97 87.37 0 bottom
PC475  EV@0.1u/25V_4  [C0402]  282.45 87.34 180 bottom
PC476  EV@0.1u/25V_4  [C0402]  223.4 87.08 180 bottom
PC477  EV@0.1u/25V_4  [C0402]  233.18 87.08 180 bottom
PC478  EV@0.1u/25V_4  [C0402]  242.95 87.08 180 bottom
PC479  EV@0.1u/25V_4  [C0402]  252.73 87.08 180 bottom
PC480  EV@0.1u/25V_4  [C0402]  262.51 87.08 180 bottom
PC481  EV@0.1u/25V_4  [C0402]  272.29 87.08 180 bottom
PC482  0.1u/50V_4  [C0402]  55.86 69 90 bottom
PC483  0.1u/50V_4  [C0402]  256.33 62.52 90 bottom
PC484  1u/6.3V_2  [C0201]  265.4 62.2 270 bottom
PC485  22u/6.3V_6  [C0603]  257.55 62.06 90 bottom
PC486  *68p/50V_4  [C0402]  266.28 61.84 90 bottom
PC487  *0.1u/50V_4  [C0402]  262.43 61 90 bottom
PC488  33u/25V_D6.3H4.5  [ECAP6_3X7_7-7_8]  139.77 51.17 0 bottom
PC489  22u/6.3V_8  [C0805]  133.56 51.52 180 bottom
PC490  33u/25V_D6.3H4.5  [ECAP6_3X7_7-7_8]  172.56 51.17 180 bottom
PC491  22u/6.3V_8  [C0805]  126.14 51.12 0 bottom
PC492  10u/25V_8  [C0805]  147.15 50.18 90 bottom
PC493  10u/25V_8  [C0805]  166.5 50.14 90 bottom
PC494  0.1u/50V_4  [C0402]  133.99 50.05 180 bottom
PC495  2200p/50V_4  [C0402]  145.65 49.77 90 bottom
PC496  0.1u/50V_4  [C0402]  144.66 49.41 90 bottom
PC497  2200p/50V_4  [C0402]  168.02 49.38 90 bottom
PC498  10u/25V_8  [C0805]  45.85 49.04 180 bottom
PC499  1u/6.3V_2  [C0201]  115.6 48.83 90 bottom
PC500  0.1u/50V_4  [C0402]  119.92 48.2 180 bottom
PC501  0.1u/50V_4  [C0402]  135.79 46.37 270 bottom
PC502  2200p/50V_4  [C0402]  46.56 46.7 180 bottom
PC503  0.1u/50V_4  [C0402]  169.83 46.62 270 bottom
PC504  1u/6.3V_4  [C0402]  244.35 45.68 270 bottom
PC505  *0.1u/50V_4  [C0402]  111.86 44.79 90 bottom
PC506  10u/6.3V_6  [C0603]  120.04 43.63 90 bottom
PC507  220u/6.3V_D6.3H4.2  [ECAP6_3X4_6-7_3-2P]  137.17 41.96 90 bottom
PC508  10u/6.3V_4  [C0402_2]  117.94 42.41 90 bottom
PC509  220u/6.3V_D6.3H4.2  [ECAP6_3X4_6-7_3-2P]  174.66 42.58 90 bottom
PC510  *0.1u/50V_4  [C0402]  111.92 41.97 90 bottom
PC511  0.1u/50V_4  [C0402]  114.07 41.97 90 bottom
PC512  0.033u/16V_4  [C0402]  115.85 41.97 90 bottom
PC513  0.1u/50V_4  [C0402]  120.3 41.7 0 bottom
PC514  2200p/50V_4  [C0402]  126.93 41.7 180 bottom
PC515  10u/25V_8  [C0805]  128.4 39.67 180 bottom
PC516  0.1u/6.3V_2  [C0201]  226.32 38.35 270 bottom
PC517  22u/6.3V_6  [C0603]  227.39 38.22 90 bottom
PC518  *22u/6.3V_6  [C0603]  228.84 38.22 90 bottom
PC519  *22u/6.3V_6  [C0603]  230.31 38.22 90 bottom
PC520  *0.1u/16V_4  [C0402]  241.64 37.6 270 bottom
PC521  18p/25V_2  [C0201]  88.65 93.18 270 top
PC522  18p/25V_2  [C0201]  223.42 91.71 270 top
PC523  18p/25V_2  [C0201]  97.41 92.42 180 top
PC524  18p/25V_2  [C0201]  232.18 37.89 90 top
PC525  18p/25V_2  [C0201]  231.47 37.89 90 top
PC526  18p/25V_2  [C0201]  230.76 37.89 90 top
PC527  18p/25V_2  [C0201]  244.3 40.68 0 top
PD1  EV@1SS355  [D-1_85X1_25-2P-0_95H]  201.6 105.55 0 top
PD2  *EV@RB500V-40  [D-1_85X1_25-2P-0_95H]  279.53 83.83 90 top
PD3  BAT54CW  [SOT23-1_7-65-3P]  42.8 48.22 90 top
PD4  PDZ5.6B  [D-SOD323-1_7X1_25-PMEG4005AEA]  78.54 42.81 270 top
PD5  PDZ5.6B  [D-SOD323-1_7X1_25-PMEG4005AEA]  75.19 42.71 270 top
PD6  MESMAF20A  [D-3_8X2_5]  172.91 213.43 90 bottom
PD7  G3@MESMAF20A  [D-3_8X2_5]  223.44 206.46 90 bottom
PJ1  *sEV@0.002_1%_0612  [S0612]  285.93 134.91 270 top
PJ2  *sEV@0.002_1%_0612  [S0612]  286.01 118.33 270 top
PJ3  *s5G@0.002_1%_0612  [S0612]  299.9 107.53 90 top
PJ4  *s5G@0.002_1%_0612  [S0612]  297.06 94.32 90 top
PJ5  *s0_5%_8  [S0805]  266.83 67.27 90 top
PJ6  *s0_5%_8  [S0805]  255.15 60.92 90 top
PJ7  *s0.002_1%_0612  [S0612]  225.33 41.19 90 top
PJ8  2DC3207-000111F  [DCJK-2DC3207-000111F-3P]  183.9 214.6 0 bottom
PJ9  G3@2DC3207-000111F  [DCJK-2DC3207-000111F-3P]  211.9 214.6 0 bottom
PJ10  EV@0.005_1%_2037  [RC2037-SMT]  136.71 205.42 0 bottom
PJ11  *s0.002_1%_0612  [S0612]  170.82 202.4 90 bottom
PJ12  *s0_5%_8  [S0805]  202.06 94.91 270 bottom
PJ13  *s0.002_1%_0612  [S0612]  146.18 53.81 90 bottom
PJ14  *s0.002_1%_0612  [S0612]  167.08 53.68 270 bottom
PJ15  *s0.002_1%_0612  [S0612]  130.03 52.06 90 bottom
PJ16  *s0.002_1%_0612  [S0612]  178.31 47.82 270 bottom
PJ17  *s0.002_1%_0612  [S0612]  142.1 47.23 270 bottom
PJ18  *s0.002_1%_0612  [S0612]  246.56 43.14 90 bottom
PJ19  50458-01001-V02  [WTB-50458-01001-V02-10P-L]  72.55 41.52 180 bottom
PJ20  *s0.002_1%_0612  [S0612]  124.08 40.6 270 bottom
PL1  5G@3.3uH_5x5x1.8  [CHOKE-PCMB051H-3R3MS]  297.8 98.87 180 top
PL2  3.3uH_5x5x1.8  [CHOKE-PCMB051H-3R3MS]  92.84 95.63 0 top
PL3  1uH_5x5x1.8  [L5_1X5_2-1_6H]  258.16 65.48 180 top
PL4  EV@0.36uH/30A_10x10x4  [L10X10-3_8]  257.13 196.05 180 bottom
PL5  EV@0.36uH/30A_10x10x4  [L10X10-3_8]  240.77 195.87 0 bottom
PL6  0.24uH/28A_7x7x4  [L6_6X6_6-3_8]  171.2 189.47 270 bottom
PL7  0.22uH/45A_12x8x4  [L11_5X7_9-3_8H]  113.92 183.99 270 bottom
PL8  0.22uH/45A_12x8x4  [L11_5X7_9-3_8H]  123.57 183.99 270 bottom
PL9  0.22uH/45A_12x8x4  [L11_5X7_9-3_8H]  133.23 183.99 270 bottom
PL10  0.22uH/45A_12x8x4  [L11_5X7_9-3_8H]  142.88 183.99 270 bottom
PL11  0.22uH/45A_12x8x4  [L11_5X7_9-3_8H]  152.53 183.99 270 bottom
PL12  0.22uH/45A_12x8x4  [L11_5X7_9-3_8H]  162.18 183.99 270 bottom
PL13  EV@1.5uH_7x7x3  [L6_6X6_6-3H]  286.42 128.8 90 bottom
PL14  EV@0.22uH/45A_12x8x4  [L11_5X7_9-3_8H]  277.73 102.96 90 bottom
PL15  G3@0.22uH/45A_12x8x4  [L11_5X7_9-3_8H]  287.25 102.96 90 bottom
PL16  EV@0.22uH/45A_12x8x4  [L11_5X7_9-3_8H]  220.58 102.71 90 bottom
PL17  EV@0.22uH/45A_12x8x4  [L11_5X7_9-3_8H]  230.1 102.71 90 bottom
PL18  EV@0.22uH/45A_12x8x4  [L11_5X7_9-3_8H]  239.63 102.71 90 bottom
PL19  EV@0.22uH/45A_12x8x4  [L11_5X7_9-3_8H]  249.15 102.71 90 bottom
PL20  EV@0.22uH/45A_12x8x4  [L11_5X7_9-3_8H]  258.68 102.71 90 bottom
PL21  EV@0.22uH/45A_12x8x4  [L11_5X7_9-3_8H]  268.2 102.71 90 bottom
PL22  2.2uH_2.5x2.0x1.2  [L2_5X2-1_2H]  201.51 91.47 90 bottom
PL23  1uH/11A_7x7x3  [L6_6X6_6-2_8H]  130.05 45.81 90 bottom
PL24  2.2uH_10x10x4  [L10_3X10-4H-SMT]  149.48 43.24 0 bottom
PL25  2.2uH_10x10x4  [L10_3X10-4H-SMT]  163.89 43.22 0 bottom
PL26  6.8uH_7x7x3  [L6_6X6_6-2_8H]  52.48 41.62 0 bottom
PL27  0.24uH_7x7x4  [L6_6X6_6-3_8]  235.54 41.11 180 bottom
PQ1  EV@PJE8406  [SOT23-1_38-5-3P]  258.88 215.31 0 top
PQ2  EV@PJE8406  [SOT23-1_38-5-3P]  261.41 215.18 0 top
PQ3  *PJA138K  [SOT23-2-95-3P]  169.5 215 0 top
PQ4  EV@2N7002K  [SOT23-2-95-3P]  256.85 212.44 90 top
PQ5  EV@METR3904-G  [SOT23-2-95-3P]  260.99 212.32 0 top
PQ6  2N7002KW  [SOT23-1_7-65-3P]  195.25 205.98 90 top
PQ7  2N7002KW  [SOT23-1_7-65-3P]  200.59 205.96 90 top
PQ8  2N7002KW  [SOT23-1_7-65-3P]  197.95 205.83 90 top
PQ9  G3@2N7002KW  [SOT23-1_7-65-3P]  233.28 205.52 180 top
PQ10  G3@2N7002KW  [SOT23-1_7-65-3P]  228.74 204.96 90 top
PQ11  *EV@METR3904-G  [SOT23-2-95-3P]  223.65 203.54 90 top
PQ12  G3@2N7002K  [SOT23-2-95-3P]  179.07 175.86 180 top
PQ13  EV@2N7002K  [SOT23-2-95-3P]  207.89 104.9 0 top
PQ14  EV@AONR32320C  [POWER-3X3-65-5P-ADNR21357]  201.92 102.13 90 top
PQ15  2N7002KTB  [SOT23-1_38-5-3P]  83.95 92.67 0 top
PQ16  DDTC144EUA-7-F  [SOT23-1_7-65-3P]  86.54 87.6 0 top
PQ17  *EV@PJE8406  [SOT23-1_38-5-3P]  281.56 86.07 180 top
PQ18  *EV@2N7002KTB  [SOT23-1_38-5-3P]  282.55 83.79 180 top
PQ19  EV@PJE8406  [SOT23-1_38-5-3P]  275.9 83.66 270 top
PQ20  EV@2N7002K  [SOT23-2-95-3P]  272.8 83.53 90 top
PQ21  AOSS32334C  [SOT23-2_38-95-3P]  252.99 65.43 270 top
PQ22  2N7002K  [SOT23-2-95-3P]  249.38 64.53 270 top
PQ23  *2N7002K  [SOT23-2-95-3P]  59.03 64.25 270 top
PQ24  2N7002K  [SOT23-2-95-3P]  62.56 64.25 270 top
PQ25  *2N7002K  [SOT23-2-95-3P]  68.76 63.89 270 top
PQ26  *DDTC144EUA-7-F  [SOT23-1_7-65-3P]  65.66 63.87 90 top
PQ27  DDTC144EUA-7-F  [SOT23-1_7-65-3P]  60.28 61.08 270 top
PQ28  2N7002K  [SOT23-2-95-3P]  249.56 60.92 180 top
PQ29  AOSS32334C  [SOT23-2_38-95-3P]  55.94 55.71 270 top
PQ30  2N7002K  [SOT23-2-95-3P]  59.52 54.77 270 top
PQ33  2N7002K  [SOT23-2-95-3P]  56.06 52 0 top
PQ34  DDTC144EUA-7-F  [SOT23-1_7-65-3P]  59.4 51.8 0 top
PQ35  *2N7002K  [SOT23-2-95-3P]  61.6 49.27 270 top
PQ36  AONS32310  [POWER-5_2X5_55-1_27-5P]  54.49 45.43 270 top
PQ37  PJA3411  [SOT23-2-95-3P]  30.86 44.69 270 top
PQ38  2N7002KW  [SOT23-1_7-65-3P]  31.25 41.52 270 top
PQ39  *2N7002K  [SOT23-2-95-3P]  169.53 214.39 0 bottom
PQ40  G3@2N7002KW  [SOT23-1_7-65-3P]  233.2 205.8 0 bottom
PQ41  EV@AOE6936  [POWER-5X6-1_27-10P]  256.36 204.79 0 bottom
PQ42  EV@AOE6936  [POWER-5X6-1_27-10P]  262.52 204.77 0 bottom
PQ43  EV@AOE6936  [POWER-5X6-1_27-10P]  244.89 204.51 0 bottom
PQ44  EV@AOE6936  [POWER-5X6-1_27-10P]  238.82 204.47 0 bottom
PQ45  G3@AONS21309C  [POWER-5_2X5_55-1_27-5P]  206.67 199.94 180 bottom
PQ46  G3@AONS21309C  [POWER-5_2X5_55-1_27-5P]  223.15 199.94 180 bottom
PQ47  G3@AONS21309C  [POWER-5_2X5_55-1_27-5P]  213.85 199.91 0 bottom
PQ48  AONS21309C  [POWER-5_2X5_55-1_27-5P]  183.43 199.56 0 bottom
PQ49  AONS21309C  [POWER-5_2X5_55-1_27-5P]  190.68 199.56 180 bottom
PQ50  G3@AONS21309C  [POWER-5_2X5_55-1_27-5P]  197.53 199.53 0 bottom
PQ51  2N7002K  [SOT23-2-95-3P]  177.96 198.24 90 bottom
PQ52  AOE6932  [POWER-5X6-1_27-10P]  170.31 197.49 0 bottom
PQ53  G3@2N7002K  [SOT23-2-95-3P]  212.72 193.9 270 bottom
PQ54  G3@2N7002K  [SOT23-2-95-3P]  202.93 193.89 270 bottom
PQ55  G3@2N7002K  [SOT23-2-95-3P]  217.26 193.83 270 bottom
PQ56  G3@2N7002K  [SOT23-2-95-3P]  208.36 193.68 270 bottom
PQ57  G3@2N7002K  [SOT23-2-95-3P]  195.96 193.51 270 bottom
PQ58  AONS32310  [POWER-5_2X5_55-1_27-5P]  188.45 191.38 180 bottom
PQ59  AONS32310  [POWER-5_2X5_55-1_27-5P]  179.84 191.25 0 bottom
PQ60  G3@AONS21309C  [POWER-5_2X5_55-1_27-5P]  186.87 179.62 0 bottom
PQ61  G3@2N7002K  [SOT23-2-95-3P]  181.92 175.88 270 bottom
PQ62  G3@2N7002K  [SOT23-2-95-3P]  178.31 175.86 270 bottom
PQ63  EV@PJE8406  [SOT23-1_38-5-3P]  200.79 107.28 180 bottom
PQ64  EV@2N7002K  [SOT23-2-95-3P]  208.89 104.94 90 bottom
PQ65  AONY36354  [POWER-5_2X5_55-1_27-7P-1H]  151.51 51.52 90 bottom
PQ66  AONY36354  [POWER-5_2X5_55-1_27-7P-1H]  161.8 51.27 270 bottom
PQ67  AONY36356  [POWER-5_2X5_55-1_27-7P-1H]  123.62 45.63 180 bottom
PQ68  2N7002KW  [SOT23-1_7-65-3P]  31.37 44.69 90 bottom
PQ69  AONR32320C  [POWER-3X3-65-5P-ADNR21357]  45.81 44.17 0 bottom
PQ70  PJA3411  [SOT23-2-95-3P]  30.86 41.14 90 bottom
PQ71  AONR36326C  [POWER-3X3-65-5P-ADNR21357]  45.81 40.1 180 bottom
PQ72  5G@DDTC144EUA-7-F  [SOT23-1_7-65-3P]  303.21 100.14 270 bottom
PQ73  5G@2N7002K  [SOT23-2-95-3P]  299.23 107.63 270 bottom
PR1  EV@1M_5%_2  [R0201]  259.58 216.81 180 top
PR2  100_1%_2  [R0201]  126.62 216.5 180 top
PR3  *EV@10K_1%_2  [R0201]  229.01 216.4 90 top
PR4  EV@10K_1%_2  [R0201]  225.12 216.24 270 top
PR5  EV@31.6K_1%_2  [R0201]  225.84 216.24 90 top
PR6  *sEV@0_5%_2  [S0201]  226.55 216.24 270 top
PR7  *EV@324K_1%_4  [R0402]  227.78 216.15 180 top
PR8  *sEV@0_5%_2  [S0201]  232.55 215.92 90 top
PR9  *22_5%_8  [R0805]  166.02 215.87 180 top
PR10  EV@10K_1%_2  [R0201]  229.75 215.86 270 top
PR11  EV@22_5%_8  [R0805]  256.6 215.81 270 top
PR12  *s0_5%_2  [S0201]  126.62 215.74 180 top
PR13  *sEV@0_5%_2  [S0201]  233.33 215.71 90 top
PR14  *EV@0_5%_2  [R0201]  250.11 215.58 180 top
PR15  EV@10K_1%_2  [R0201]  228.1 215.3 0 top
PR16  *sEV@0_5%_2  [S0201]  225.81 215.26 90 top
PR17  *EV@0_5%_2  [R0201]  225.09 215.26 90 top
PR18  *sEV@0_5%_2  [S0201]  231.8 215.01 180 top
PR19  *s0_5%_2  [S0201]  126.62 214.97 180 top
PR20  *sEV@0_5%_2  [S0201]  263.18 214.67 180 top
PR21  *100K_1%_2  [R0201]  163.55 214.64 180 top
PR22  100K_1%_2  [R0201]  162.56 214.63 180 top
PR23  *s0_5%_4  [S0402]  161.52 214.34 270 top
PR24  *EV@0_5%_2  [R0201]  232.6 214.12 90 top
PR25  *sEV@0_5%_2  [S0201]  225.13 213.88 270 top
PR26  *EV@90.9K_1%_4  [R0402]  223.19 213.87 0 top
PR27  100K_1%_2  [R0201]  162.56 213.83 180 top
PR28  *100K_1%_2  [R0201]  163.55 213.83 180 top
PR29  100K_1%_2  [R0201]  125.67 213.81 0 top
PR30  EV@100K_1%_2  [R0201]  258.97 213.72 90 top
PR31  *1M_5%_2  [R0201]  165.77 213.7 180 top
PR32  *EV@0_5%_2  [R0201]  224.41 213.63 270 top
PR33  *100K_1%_4  [R0402]  167.43 213.33 180 top
PR34  *EV@0_5%_2  [R0201]  233.21 213.18 0 top
PR35  EV@75K_1%_2  [R0201]  263.48 213.08 90 top
PR36  EV@100K_1%_2  [R0201]  258.97 212.73 270 top
PR37  2.2_5%_6  [R0603]  165.24 212.43 0 top
PR38  G3@120K_1%_4  [R0402]  143.64 212.41 0 top
PR39  *EV@10K_1%_2  [R0201]  225.33 212.4 90 top
PR40  EV@10K_1%_2  [R0201]  223.9 212.4 90 top
PR41  *EV@10K_1%_2  [R0201]  224.62 212.39 90 top
PR42  *EV@0_5%_2  [R0201]  233.45 212.19 0 top
PR43  *EV@100K_1%_2  [R0201]  263.14 212.09 270 top
PR44  23.7K_1%_4  [R0402]  161.93 211.93 270 top
PR45  EV@1M_5%_2  [R0201]  258.97 211.75 270 top
PR46  *10K_1%_4  [R0402]  167.07 211.52 90 top
PR47  *sEV@0_5%_2  [S0201]  233.45 211.42 0 top
PR48  G3@100K_1%_2  [R0201]  143.67 211.34 180 top
PR49  EV@10K_1%_2  [R0201]  224.18 211.16 270 top
PR50  EV@15K_1%_2  [R0201]  247.05 210.85 270 top
PR51  *s0_5%_2  [S0201]  163.88 210.48 270 top
PR52  *s0_5%_2  [S0201]  164.65 210.48 270 top
PR53  220_1%_2  [R0201]  163.1 210.47 90 top
PR54  *sEV@0_5%_2  [S0201]  225.71 211.04 0 top
PR55  *sEV@0_5%_2  [S0201]  233.43 210.29 180 top
PR56  *s0_5%_2  [S0201]  167.14 210.27 180 top
PR57  30.1K_1%_2  [R0201]  169.04 210.02 0 top
PR58  G3@100K_1%_2  [R0201]  142.24 209.84 180 top
PR59  17.8K_1%_2  [R0201]  161.17 209.84 0 top
PR60  EV@10K_1%_2  [R0201]  225.12 209.59 0 top
PR61  *sG3@0_5%_2  [S0201]  143.47 209.54 270 top
PR62  *G3@0_5%_2  [R0201]  144.22 209.54 270 top
PR63  *EV@0_5%_2  [R0201]  233.95 209.38 180 top
PR64  *EV@0_5%_2  [R0201]  232.95 209.38 180 top
PR65  15K_1%_2  [R0201]  162.06 209.1 90 top
PR66  90.9K_1%_2  [R0201]  161.14 209 0 top
PR67  *sEV@0_5%_2  [S0201]  232.96 208.55 0 top
PR68  150K_1%_2  [R0201]  160.2 208.37 90 top
PR69  *sEV@0_5%_2  [S0201]  225.72 208.34 270 top
PR70  100_1%_2  [R0201]  169.07 208.32 0 top
PR71  200_1%_2  [R0201]  170.69 208.12 0 top
PR72  *sEV@0_5%_2  [S0201]  231.07 208.08 90 top
PR73  *sEV@0_5%_2  [S0201]  231.79 208.08 90 top
PR74  *sEV@0_5%_2  [S0201]  230.16 208.04 90 top
PR75  *EV@649_1%_4  [R0402]  227.59 207.71 270 top
PR76  G3@1M_5%_2  [R0201]  234.79 207.62 90 top
PR77  14.3K_1%_2  [R0201]  167.9 207.61 270 top
PR78  *sEV@0_5%_2  [S0201]  225.73 207.35 90 top
PR79  *sEV@0_5%_2  [S0201]  228.56 207.23 180 top
PR80  10K_1%_2  [R0201]  161.93 207.23 0 top
PR81  10K_1%_2  [R0201]  170.69 207.1 180 top
PR82  *sEV@0_5%_2  [S0201]  229.55 207.1 0 top
PR83  *EV@649_1%_4  [R0402]  230.9 207.06 0 top
PR84  G3@1M_5%_2  [R0201]  234.79 206.56 270 top
PR85  *s0_5%_2  [S0201]  161.93 206.46 0 top
PR86  *EV@357_1%_2  [R0201]  226.74 206.35 90 top
PR87  5.11K_1%_4  [R0402]  169.04 206.21 270 top
PR88  100_1%_2  [R0201]  170.18 206.08 270 top
PR89  15K_1%_2  [R0201]  161.93 205.7 0 top
PR90  G3@200K_5%_2  [R0201]  230.53 205.68 270 top
PR91  *EV@49.9K_1%_2  [R0201]  224.54 205.58 180 top
PR92  4.7K_1%_4  [R0402]  168.35 204.79 0 top
PR93  *sG3@0_5%_4  [S0402]  230.53 203.94 270 top
PR94  G3@1M_5%_2  [R0201]  232.71 203.82 180 top
PR95  *s0_5%_4  [S0402]  197.37 203.81 180 top
PR96  100K_1%_2  [R0201]  199.19 203.72 0 top
PR97  *s0_5%_4  [S0402]  201.04 203.67 180 top
PR98  G3@1M_5%_2  [R0201]  232.71 203.1 0 top
PR99  2.2_5%_6  [R0603]  165.64 203 0 top
PR100  *EV@2.2_5%_6  [R0603]  235.63 200.67 180 top
PR101  *s0_5%_2  [S0201]  226.24 192.02 90 top
PR102  *s0_5%_2  [S0201]  226.98 192.02 90 top
PR103  *sG3@0_5%_4  [S0402]  226.08 190.45 180 top
PR104  *sG3@0_5%_2  [S0201]  224.43 190.41 180 top
PR105  2.2_1%_6  [R0603]  117.22 190.34 90 top
PR106  2.2_1%_6  [R0603]  136.4 190.34 90 top
PR107  2.2_1%_6  [R0603]  126.62 190.21 90 top
PR108  2.2_1%_6  [R0603]  145.93 190.21 90 top
PR109  2.2_1%_6  [R0603]  155.71 190.21 90 top
PR110  2.2_1%_6  [R0603]  165.23 190.21 90 top
PR111  *sG3@0_5%_2  [S0201]  228.95 190.13 0 top
PR112  *sG3@0_5%_2  [S0201]  223.2 187.81 0 top
PR113  *sEV@0_5%_2  [S0201]  233.68 187.28 0 top
PR114  EV@10_1%_2  [R0201]  234.68 187.28 0 top
PR115  *sG3@0_5%_2  [S0201]  227.51 187.21 0 top
PR116  *s0_5%_2  [S0201]  166.4 150.1 270 top
PR117  *s0_5%_2  [S0201]  167.14 150.1 270 top
PR118  EV@10K_1%_2  [R0201]  291.17 124.07 180 top
PR119  EV@1_1%_6  [R0603]  284.82 122.63 0 top
PR120  EV@20.5K_1%_2  [R0201]  291.6 121.12 0 top
PR121  *sEV@0_5%_2  [S0201]  291.6 120.26 180 top
PR122  EV@1K_1%_2  [R0201]  289.5 119.44 90 top
PR123  *Short_0201  [S0201]  291.34 119.29 270 top
PR124  *EV@2.2_5%_6  [R0603]  288.69 117.01 270 top
PR125  5G@10K_1%_2  [R0201]  297.5 106.18 180 top
PR126  5G@1K_1%_2  [R0201]  295.69 105.74 0 top
PR127  EV@10K_1%_2  [R0201]  203.74 105.53 90 top
PR128  *5G@10K_1%_2  [R0201]  295.65 104.99 0 top
PR129  5G@45.3K_1%_4  [R0402]  295.28 102.99 0 top
PR130  EV@110_1%_4  [R0402]  199.39 103.36 90 top
PR131  *s5G@0_5%_2  [S0201]  294.82 102.1 180 top
PR132  EV@10K_1%_2  [R0201]  199.49 101.86 270 top
PR133  EV@5.6_5%_8  [R0805]  206.95 101.41 180 top
PR134  EV@100_1%_4  [R0402]  204.84 101.19 90 top
PR135  *sEV@0_5%_2  [S0201]  198.94 100.67 90 top
PR136  *s0_5%_8  [S0805]  97.16 97.37 270 top
PR137  22_5%_8  [R0805]  83.44 94.96 0 top
PR138  *s0_5%_8  [S0805]  87.38 90.89 0 top
PR139  1M_5%_6  [R0603]  84.05 90.81 0 top
PR140  1M_5%_6  [R0603]  84.05 89.28 180 top
PR141  *Short_0201  [S0201]  96.61 88.31 90 top
PR142  *Short_0201  [S0201]  88.56 87.11 90 top
PR143  *100K_1%_2  [R0201]  89.33 87.11 270 top
PR144  *EV@1M_5%_2  [R0201]  283.32 86.45 0 top
PR145  *EV@0_5%_2  [R0201]  279.65 85.97 180 top
PR146  *EV@100K_1%_2  [R0201]  283.32 85.69 180 top
PR147  200K_5%_2  [R0201]  90.94 85.56 270 top
PR148  10K_1%_2  [R0201]  93.48 85.43 90 top
PR149  *s0_5%_2  [S0201]  94.49 85.43 90 top
PR150  *s0_5%_2  [S0201]  95.51 85.43 90 top
PR151  *s0_5%_2  [S0201]  96.52 85.43 90 top
PR152  *10K_1%_2  [R0201]  88.24 85.39 270 top
PR153  18.2K_1%_2  [R0201]  90.94 84.16 270 top
PR154  *s0_5%_2  [S0201]  88.24 83.92 270 top
PR155  EV@180K_1%_2  [R0201]  254.51 83.91 270 top
PR156  EV@37.4K_1%_2  [R0201]  255.65 83.91 270 top
PR157  EV@37.4K_1%_2  [R0201]  256.92 83.91 270 top
PR158  EV@27.4K_1%_2  [R0201]  258.07 83.91 270 top
PR159  EV@36K_1%_2  [R0201]  259.21 83.91 270 top
PR160  EV@100K_1%_2  [R0201]  260.35 83.91 270 top
